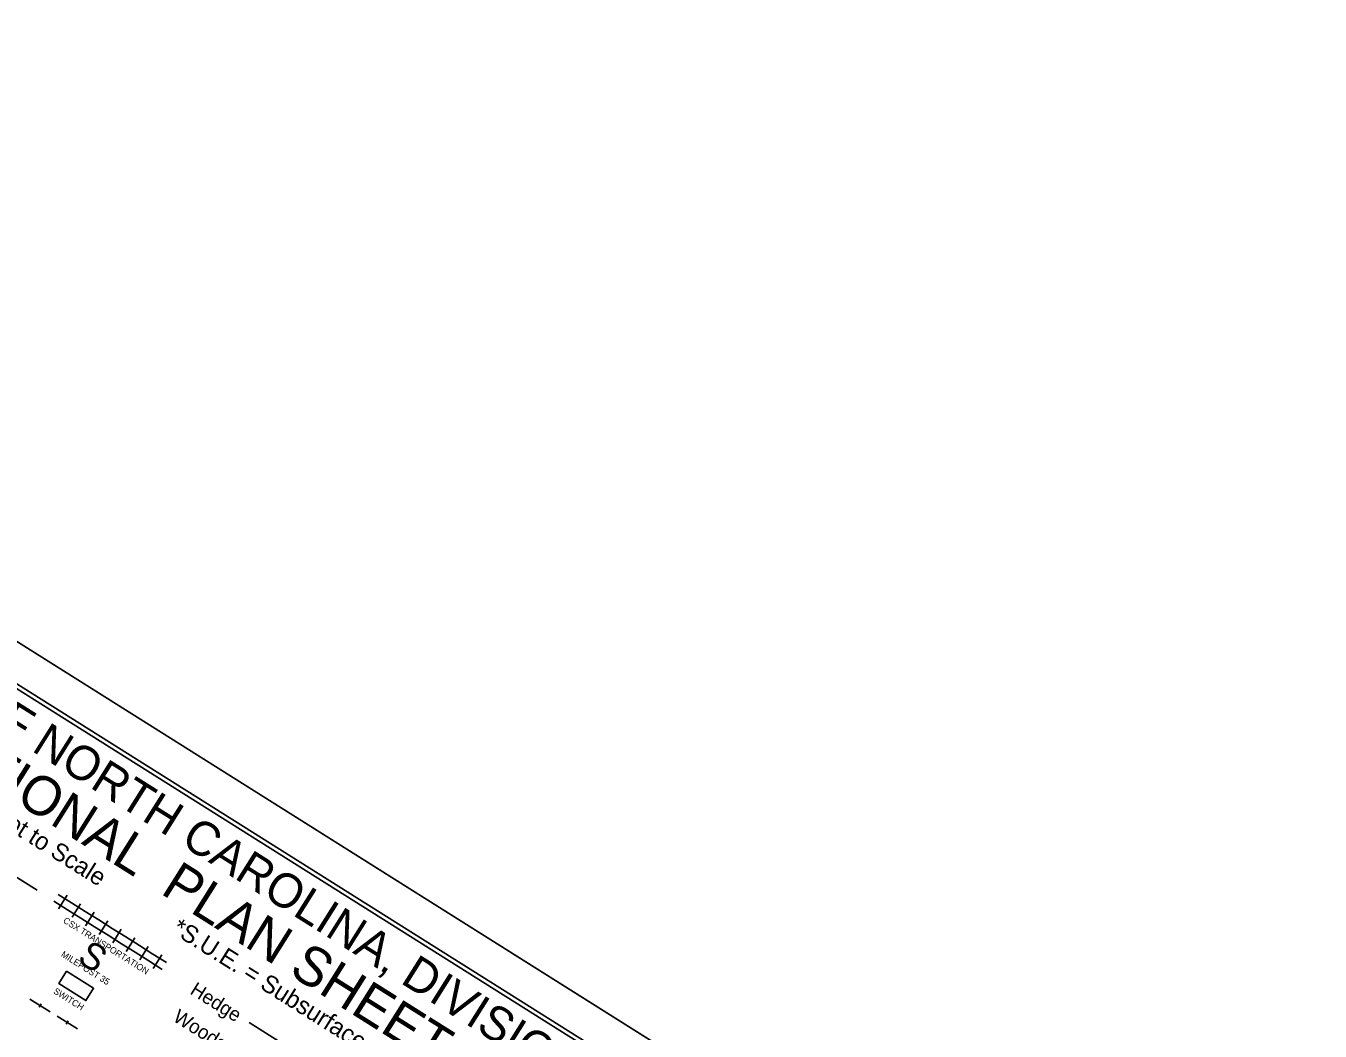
# Model space of a CAD drawing. Extents: x 2337092 to 2349158, y 800756 to 811724.
# Drawn here: x 2344308 to 2349158, y 807955 to 811724 of the extents above; entities that cross this region are included whole.
import ezdxf

# ---------------------------------------------------------------- set-up
doc = ezdxf.new("R2010")
doc.units = 0
for name, color, linetype in [('Sheet Cutting Line CELL', 7, 'Continuous'), ('Sheet Plot Border Inside CELL', 7, 'Continuous'), ('Sheet Plot Border Outside CELL', 7, 'Continuous'), ('Sheet Symbology CELL', 7, 'Continuous')]:
    doc.layers.add(name, color=color, linetype=linetype)

msp = doc.modelspace()

# ---------------------------------------------------------------- linework, layer by layer
at = {"layer": 'Sheet Cutting Line CELL'}
msp.add_line((2349158.5, 806341.3), (2340607.3, 811723.5), dxfattribs=at)
at = {"layer": 'Sheet Plot Border Inside CELL'}
msp.add_lwpolyline([(2337229.4, 806210.3), (2345691.7, 800884), (2349063.9, 806241.7), (2340601.5, 811568)], close=True, dxfattribs=at)
at = {"layer": 'Sheet Plot Border Outside CELL'}
msp.add_lwpolyline([(2337091.6, 806137.8), (2345642.8, 800755.6), (2349158.5, 806341.3), (2340607.3, 811723.5)], close=True, dxfattribs=at)
at = {"layer": 'Sheet Symbology CELL'}
for p, q in [((2344350.2, 808483.4), (2343545.8, 808989.7)), ((2344428.3, 808468), (2344479.1, 808436)), ((2344429.8, 808413.9), (2344461.7, 808464.7)), ((2344412.4, 808442.6), (2344463.1, 808410.6)), ((2344463.1, 808410.6), (2344513.9, 808378.7)), ((2344479.1, 808436), (2344529.9, 808404.1)), ((2344480.5, 808382), (2344512.5, 808432.7)), ((2344513.9, 808378.7), (2344564.7, 808346.7)), ((2344529.9, 808404.1), (2344580.7, 808372.1)), ((2344531.3, 808350), (2344563.3, 808400.8)), ((2344580.7, 808372.1), (2344631.5, 808340.1)), ((2344582.1, 808318), (2344614.1, 808368.8)), ((2344564.7, 808346.7), (2344615.5, 808314.8)), ((2344615.5, 808314.8), (2344666.3, 808282.8)), ((2344631.5, 808340.1), (2344682.2, 808308.2)), ((2344632.9, 808286.1), (2344664.8, 808336.9)), ((2344666.3, 808282.8), (2344717, 808250.8)), ((2344682.2, 808308.2), (2344733, 808276.2)), ((2344683.7, 808254.1), (2344715.6, 808304.9)), ((2344733, 808276.2), (2344783.8, 808244.3)), ((2344734.4, 808222.2), (2344766.4, 808272.9)), ((2344717, 808250.8), (2344767.8, 808218.9)), ((2344767.8, 808218.9), (2344818.6, 808186.9)), ((2344783.8, 808244.3), (2344834.6, 808212.3)), ((2344785.2, 808190.2), (2344817.2, 808241)), ((2344322.9, 808075.2), (2344399.1, 808027.3)), ((2344365, 808057.6), (2344357, 808044.9)), ((2344424.5, 808011.3), (2344500.6, 807963.3)), ((2344466.6, 807993.7), (2344458.6, 807981)), ((2346224.2, 807308.1), (2345144.1, 807987.8))]:
    msp.add_line(p, q, dxfattribs=at)
for points in [[(2348992.3, 806268.7), (2341375.4, 811062.8), (2338022.8, 805736.2), (2345639.6, 800942.1)], [(2344459.9, 808180.2), (2344561.4, 808116.2), (2344532.3, 808070), (2344430.8, 808133.9)]]:
    msp.add_lwpolyline(points, close=True, dxfattribs=at)

# ---------------------------------------------------------------- texts
for s, height, p in [('STATE OF NORTH CAROLINA, DIVISION OF HIGHWAYS', 128.514, (2343573.9, 809480.8)), ('CONVENTIONAL  PLAN SHEET SYMBOLS', 146.882, (2343404.1, 809356.8)), ('Note: Not to Scale', 66, (2343975.1, 808877.2)), ('CSX TRANSPORTATION', 24, (2344444.8, 808363.8)), ('*S.U.E. = Subsurface Utility Engineering', 66, (2344850.9, 808325.9)), ('S', 99, (2344495.7, 808217.2)), ('MILEPOST 35', 24, (2344437.1, 808236.9)), ('Hedge', 52.5, (2344919.1, 808097.4)), ('SWITCH', 24, (2344408.4, 808099)), ('Woods Line', 52.5, (2344855.2, 807995.9))]:
    msp.add_text(s, height=height, rotation=327.8134, dxfattribs=at).set_placement(p)

doc.saveas('drawing.dxf')
